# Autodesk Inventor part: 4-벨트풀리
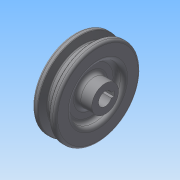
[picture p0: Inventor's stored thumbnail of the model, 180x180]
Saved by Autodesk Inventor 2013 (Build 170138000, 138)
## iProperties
Created: 2015-02
Part Number: 4-벨트풀리
Material: 일반
Document SubType Name: Modeling
Designer: Administrator
Density: 1 g/cm^3
Author: Administrator
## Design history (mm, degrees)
sketch "스케치1"
  geometry: L1 (0, 0)-(-25, 0); L2 (0, 11)-(-12, 11); L3 (-12, 11)-(-12, 21.5); L4 (-12, 21.5)-(-6, 21.5); L5 (-6, 21.5)-(-6, 35.2); L6 (-6, 35.2)-(-10.675, 35.2); L7 (-10.675, 35.2)-(-12.601, 28.9); L8 (-12.601, 28.9)-(-18.399, 28.9); L9 (-18.399, 28.9)-(-20.325, 35.2); L10 (-20.325, 35.2)-(-25, 35.2); L11 (-25, 35.2)-(-25, 21.5); L12 (-25, 21.5)-(-19, 21.5); L13 (-19, 21.5)-(-19, 11); L14 (-19, 11)-(-25, 11); L15 (-25, 11)-(-25, 5.5); L16 (-25, 5.5)-(0, 5.5); L17 (0, 5.5)-(0, 11); 2 further points
  constraints: 34 end point, 12 parallel, 4 collinear, 2 equal length, 2 point on line, 2 vertical alignment, 1 horizontal, 1 horizontal alignment, 1 perpendicular
  dimensions: "d0" = 11 diameter of L16 L1; "d2" = 22 diameter of L2 L1; "d3" = 43 diameter of L12 L1; "d4" = 8 distance of point (-11.5, 32.5) point (-19.5, 32.5); "d5" = 34 deg angle of L7 L9; "d6" = 19 distance between parallel lines of L5 L11; "d7" = 2.7 distance from line of point (-19.5, 32.5) L10; "d8" = 3.6 distance from line of L8 point (-19.5, 32.5); "d9" = 6 distance of L11.end L12.end; "d10" = 6 distance of L3.end L4.end; "d11" = 65 diameter of point (-19.5, 32.5) L1; "d12" = 25 horizontal distance of L2.start L10.end; "d13" = 25 distance of L1.start L1.end
revolve "회전1" sketch "스케치1" stored, may be unused: angle "d14" = 90 deg
sketch "스케치2"
  geometry: L1 (-2, 5.123)-(-2, 7.3); L2 (-2, 7.3)-(2, 7.3); L3 (2, 7.3)-(2, 5.123); A1 r 5.5 centre (0, 0) between (-2, 5.123) and (2, 5.123) reference
  constraints: 6 end point, 2 parallel, 2 point on circle, 1 perpendicular, 1 vertical
  dimensions: "d15" = 4 distance of L1.end L2.end; "d17" = 12.8 dimension on A1 L2
extrude "돌출1" cut sketch "스케치2" stored distance "d18" = 10; taper "d19" = 0 deg
fillet "모깎기1" dims "d20" = 2, "d21" = 0.5, "d22" = 1, "d23" = 3
node "솔리드1"
